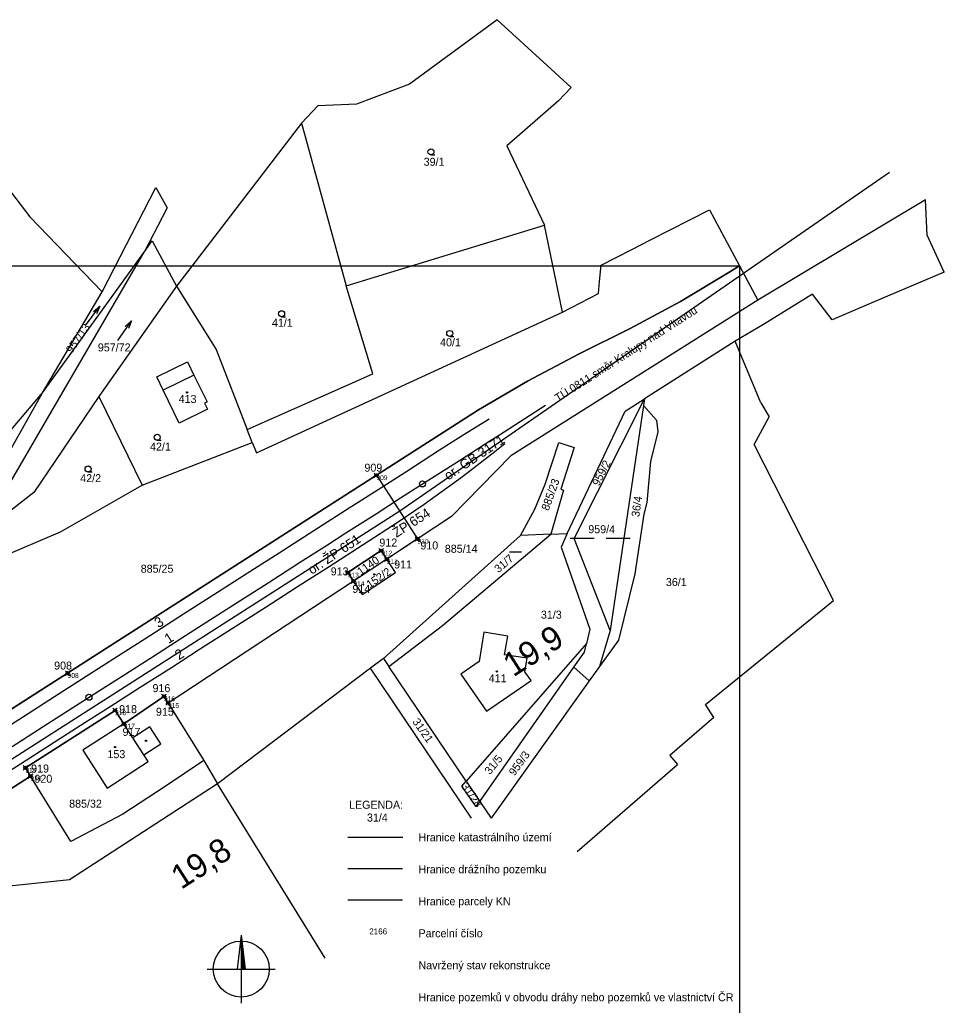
# Model space of a CAD drawing. Extents: x -752184 to -751416, y -1028299 to -1027836.
# Drawn here: x -751646.8 to -751415.5, y -1028082.5 to -1027836.1 of the extents above; entities that cross this region are included whole.
import ezdxf

# ---------------------------------------------------------------- set-up
doc = ezdxf.new("R2010")
doc.units = 0
for name, color, linetype in [('02_Osa_koleje', 7, 'Continuous'), ('03_Staničení', 7, 'Continuous'), ('Legenda', 7, 'Continuous'), ('Legenda 1', 7, 'Continuous'), ('Legenda 2', 7, 'Continuous'), ('Obvod stavby', 7, 'Continuous'), ('Vrstva 4', 7, 'Continuous'), ('Vrstva 53', 7, 'Continuous'), ('Vrstva 55', 7, 'Continuous'), ('Vrstva 56', 7, 'Continuous'), ('Vrstva 57', 7, 'Continuous'), ('Vrstva 58', 7, 'Continuous'), ('Vrstva 59', 7, 'Continuous'), ('Vrstva 60', 7, 'Continuous'), ('Vrstva 63', 7, 'Continuous'), ('VYT-BODY', 7, 'Continuous')]:
    doc.layers.add(name, color=color, linetype=linetype)

msp = doc.modelspace()

# ---------------------------------------------------------------- linework, layer by layer
at = {"layer": '02_Osa_koleje'}
for p, q in [((-751535.5, -1027939.59), (-751529.38, -1027935.82)), ((-751541.77, -1027943.62), (-751535.5, -1027939.59)), ((-751536.85, -1027946.23), (-751529.25, -1027941.37)), ((-751527.97, -1027944.03), (-751525.45, -1027941.98)), ((-751550.25, -1027949.06), (-751541.77, -1027943.62)), ((-751536.02, -1027950.26), (-751527.97, -1027944.03)), ((-751544.45, -1027951.09), (-751536.85, -1027946.23)), ((-751557.18, -1027953.5), (-751550.25, -1027949.06)), ((-751551.57, -1027955.64), (-751544.45, -1027951.09)), ((-751545.62, -1027957.19), (-751536.02, -1027950.26)), ((-751565.35, -1027958.72), (-751557.18, -1027953.5)), ((-751557.44, -1027959.4), (-751551.57, -1027955.64)), ((-751573.24, -1027963.75), (-751565.35, -1027958.72)), ((-751565.26, -1027964.39), (-751557.44, -1027959.4)), ((-751552.14, -1027961.63), (-751545.62, -1027957.19)), ((-751560.92, -1027967.3), (-751552.14, -1027961.63)), ((-751581.95, -1027969.31), (-751573.24, -1027963.75)), ((-751569.81, -1027967.31), (-751565.26, -1027964.39)), ((-751576.84, -1027971.8), (-751569.81, -1027967.31)), ((-751569.42, -1027972.75), (-751560.92, -1027967.3)), ((-751588.99, -1027973.81), (-751581.95, -1027969.31)), ((-751597.35, -1027979.15), (-751588.99, -1027973.81)), ((-751584.69, -1027976.81), (-751576.84, -1027971.8)), ((-751577.55, -1027977.95), (-751569.42, -1027972.75)), ((-751592.46, -1027981.78), (-751584.69, -1027976.81)), ((-751585.46, -1027983), (-751577.55, -1027977.95)), ((-751605.88, -1027984.61), (-751597.35, -1027979.15)), ((-751599.97, -1027986.58), (-751592.46, -1027981.78)), ((-751593.8, -1027988.33), (-751585.46, -1027983)), ((-751614.37, -1027990.06), (-751605.88, -1027984.61)), ((-751606.23, -1027990.59), (-751599.97, -1027986.58)), ((-751601.83, -1027993.46), (-751593.8, -1027988.33)), ((-751622.32, -1027995.15), (-751614.37, -1027990.06)), ((-751613.64, -1027995.33), (-751606.23, -1027990.59)), ((-751608.88, -1027997.98), (-751601.83, -1027993.46)), ((-751630.17, -1028000.17), (-751622.32, -1027995.15)), ((-751621.23, -1028000.17), (-751613.64, -1027995.33)), ((-751616.69, -1028002.97), (-751608.88, -1027997.98)), ((-751636.92, -1028004.49), (-751630.17, -1028000.17)), ((-751626.18, -1028003.34), (-751621.23, -1028000.17)), ((-751633.49, -1028008.01), (-751626.18, -1028003.34)), ((-751624.19, -1028007.75), (-751616.69, -1028002.97)), ((-751645.91, -1028010.23), (-751636.92, -1028004.49)), ((-751640.92, -1028012.76), (-751633.49, -1028008.01)), ((-751630.51, -1028011.79), (-751624.19, -1028007.75)), ((-751653.82, -1028015.29), (-751645.91, -1028010.23)), ((-751648.69, -1028017.73), (-751640.92, -1028012.76)), ((-751638.2, -1028016.71), (-751630.51, -1028011.79)), ((-751646.64, -1028022.11), (-751638.2, -1028016.71)), ((-751655.05, -1028027.47), (-751646.64, -1028022.11))]:
    msp.add_line(p, q, dxfattribs=at)
msp.add_lwpolyline([(-751529.25, -1027941.37), (-751526.83, -1027939.82), (-751515.32, -1027932.45)], dxfattribs=at)
at = {"layer": '03_Staničení'}
for centre in [(-751546.08, -1027952.12), (-751629.49, -1028005.46)]:
    msp.add_circle(centre, 0.75, dxfattribs=at)
at = {"layer": 'Legenda 1'}
for p, q in [((-751591.4, -1028064.89), (-751592.4, -1028073.39)), ((-751591.4, -1028064.89), (-751591.4, -1028081.89)), ((-751591.4, -1028064.89), (-751590.39, -1028073.39)), ((-751591.4, -1028067.02), (-751590.64, -1028073.39)), ((-751591.4, -1028069.14), (-751590.89, -1028073.39)), ((-751591.4, -1028071.27), (-751591.15, -1028073.39)), ((-751599.9, -1028073.39), (-751582.9, -1028073.39)), ((-751591.4, -1028073.39), (-751591.4, -1028073.39))]:
    msp.add_line(p, q, dxfattribs=at)
msp.add_circle((-751591.4, -1028073.39), 7, dxfattribs=at)
at = {"layer": 'Obvod stavby'}
msp.add_lwpolyline([(-751669.8, -1028021.76), (-751634.83, -1027999.42), (-751557.58, -1027949.97), (-751547.3, -1027965.87), (-751554.98, -1027970.94), (-751556.39, -1027968.8), (-751564.74, -1027974.3), (-751563.33, -1027976.45), (-751609.72, -1028006.9), (-751610.74, -1028005.23), (-751620.78, -1028012.09), (-751622.97, -1028008.73), (-751645.38, -1028023.11), (-751644.14, -1028025.2), (-751657.66, -1028033.82)], dxfattribs=at)
at = {"layer": 'Vrstva 4'}
msp.add_lwpolyline([(-751880.79, -1027897.6), (-751466.79, -1027897.6), (-751466.79, -1028188.6), (-751880.79, -1028188.6)], close=True, dxfattribs=at)
at = {"layer": 'Vrstva 53'}
msp.add_line((-751564.73, -1028048.27), (-751551.03, -1028048.27), dxfattribs=at)
for points in [[(-751934.1, -1028186.19), (-751914.9, -1028176.41), (-751903.43, -1028170.23), (-751901.96, -1028169.44), (-751904.77, -1028166.14), (-751893.52, -1028163.47), (-751890.97, -1028163.13), (-751806.75, -1028109.29), (-751808.53, -1028106.05), (-751798.29, -1028099.68), (-751750.57, -1028069.21), (-751709.61, -1028036.63), (-751702.85, -1028029.39), (-751690.7, -1028035.11), (-751634.83, -1027999.42), (-751532.07, -1027933.64), (-751519.82, -1027926.47), (-751506.87, -1027919.58), (-751494.13, -1027913.25), (-751481.54, -1027906.54), (-751469.19, -1027899.14), (-751466.79, -1027897.6)], [(-751462.19, -1027906.18), (-751523.97, -1027945.11), (-751538.82, -1027960.28), (-751554.98, -1027970.94), (-751563.33, -1027976.45), (-751609.72, -1028006.9), (-751600.73, -1028021.25), (-751610.42, -1028027.79), (-751621, -1028034.71), (-751634.07, -1028041.54), (-751644.14, -1028025.2), (-751657.66, -1028033.82)]]:
    msp.add_lwpolyline(points, dxfattribs=at)
at = {"layer": 'Vrstva 55'}
for p, q in [((-751514.9, -1027847.48), (-751527.35, -1027836.07)), ((-751514.9, -1027847.48), (-751508.89, -1027852.99)), ((-751670.74, -1027850.8), (-751644.31, -1027885.35)), ((-751572.26, -1027857.64), (-751576.37, -1027861.95)), ((-751576.37, -1027861.95), (-751607.59, -1027902.71)), ((-751576.37, -1027861.95), (-751565.18, -1027902.61)), ((-751626.22, -1027904.08), (-751612.77, -1027878.04)), ((-751612.77, -1027878.04), (-751609.94, -1027883.14)), ((-751420.23, -1027881.1), (-751462.19, -1027906.18)), ((-751419.83, -1027889.96), (-751420.23, -1027881.1)), ((-751626.22, -1027904.08), (-751644.31, -1027885.35)), ((-751609.94, -1027883.14), (-751615.69, -1027894.18)), ((-751489.04, -1027891.13), (-751474.31, -1027883.58)), ((-751474.31, -1027883.58), (-751466.79, -1027897.6)), ((-751565.18, -1027902.61), (-751515.53, -1027887.47)), ((-751511.01, -1027909.22), (-751515.53, -1027887.47)), ((-751415.54, -1027899.18), (-751419.83, -1027889.96)), ((-751615.69, -1027894.18), (-751613.65, -1027891.36)), ((-751613.65, -1027891.36), (-751607.59, -1027902.71)), ((-751493.66, -1027893.5), (-751489.04, -1027891.13)), ((-751656.71, -1027964.65), (-751615.69, -1027894.18)), ((-751641.14, -1027929.37), (-751615.69, -1027894.18)), ((-751466.79, -1027897.6), (-751469.19, -1027899.14)), ((-751466.79, -1027897.6), (-751462.19, -1027906.18)), ((-751607.59, -1027902.71), (-751626.99, -1027930.26)), ((-751641.14, -1027929.37), (-751626.22, -1027904.08)), ((-751460.76, -1027912.3), (-751467.89, -1027916.43)), ((-751467.89, -1027916.43), (-751490.52, -1027930.81)), ((-751461.44, -1027931.84), (-751467.89, -1027916.43)), ((-751612.52, -1027925.39), (-751604.88, -1027921.62)), ((-751626.99, -1027930.26), (-751616.15, -1027952.42)), ((-751490.52, -1027930.81), (-751490.76, -1027932.54)), ((-751461.44, -1027931.84), (-751459.38, -1027935.34)), ((-751490.76, -1027932.54), (-751499.13, -1027988.78)), ((-751588.69, -1027941.76), (-751589.95, -1027938.49)), ((-751616.15, -1027952.42), (-751588.69, -1027941.76)), ((-751510.79, -1027953.68), (-751513.96, -1027964.72)), ((-751521.54, -1027965.05), (-751517.93, -1027958.42)), ((-751521.54, -1027965.05), (-751555.86, -1027995.74)), ((-751513.96, -1027964.72), (-751521.54, -1027965.05)), ((-751513.96, -1027964.72), (-751509.88, -1027964.53)), ((-751554.98, -1027970.94), (-751563.33, -1027976.45)), ((-751563.33, -1027976.45), (-751609.72, -1028006.9)), ((-751499.13, -1027988.78), (-751501.78, -1027997.8)), ((-751505.06, -1027992), (-751535.11, -1028026.46)), ((-751555.86, -1027995.74), (-751559.11, -1027998.2)), ((-751555.86, -1027995.74), (-751554.45, -1027997.78)), ((-751559.11, -1027998.2), (-751597.31, -1028027.06)), ((-751535.11, -1028026.46), (-751554.45, -1027997.78)), ((-751531.7, -1028031.5), (-751508.24, -1027997.97)), ((-751508.24, -1027997.97), (-751504.35, -1028001.39)), ((-751501.78, -1027997.8), (-751504.35, -1028001.39)), ((-751504.35, -1028001.39), (-751528.9, -1028035.64)), ((-751610.74, -1028005.23), (-751609.72, -1028006.9)), ((-751609.72, -1028006.9), (-751600.73, -1028021.25)), ((-751600.73, -1028021.25), (-751597.31, -1028027.06)), ((-751570.45, -1028070.69), (-751597.31, -1028027.06)), ((-751535.11, -1028026.46), (-751531.7, -1028031.5)), ((-751531.7, -1028031.5), (-751532.76, -1028032.72)), ((-751531.7, -1028031.5), (-751528.9, -1028035.64)), ((-751564.71, -1028040.45), (-751551.01, -1028040.45)), ((-751564.75, -1028056.09), (-751551.05, -1028056.09))]:
    msp.add_line(p, q, dxfattribs=at)
for points in [[(-751527.35, -1027836.07), (-751549.35, -1027852.19), (-751562.57, -1027857.16), (-751572.26, -1027857.64)], [(-751508.89, -1027852.99), (-751512.04, -1027856.33), (-751525.01, -1027867.6), (-751515.53, -1027887.47)], [(-751511.01, -1027909.22), (-751502.05, -1027904.53), (-751501.8, -1027901.52), (-751501.41, -1027897.47), (-751493.66, -1027893.5)], [(-751469.19, -1027899.14), (-751481.54, -1027906.54), (-751494.13, -1027913.25), (-751506.87, -1027919.58), (-751519.82, -1027926.47), (-751532.07, -1027933.64), (-751634.83, -1027999.42), (-751690.7, -1028035.11), (-751702.85, -1028029.39)], [(-751415.54, -1027899.18), (-751429.76, -1027905.22), (-751434.82, -1027907.37), (-751443.56, -1027911.08)], [(-751607.59, -1027902.71), (-751597.69, -1027918.48), (-751589.95, -1027938.49)], [(-751589.95, -1027938.49), (-751558.45, -1027924.61), (-751565.18, -1027902.61)], [(-751443.56, -1027911.08), (-751448.52, -1027904.72), (-751460.76, -1027912.3)], [(-751462.19, -1027906.18), (-751523.97, -1027945.11), (-751538.82, -1027960.28), (-751554.98, -1027970.94)], [(-751588.69, -1027941.76), (-751587.61, -1027944.36), (-751511.01, -1027909.22)], [(-751604.88, -1027921.62), (-751603.25, -1027924.91), (-751599.95, -1027931.6), (-751600.61, -1027931.93), (-751599.87, -1027933.41), (-751606.96, -1027936.93), (-751610.94, -1027928.67), (-751612.52, -1027925.39)], [(-751672, -1027960.17), (-751661.99, -1027953.87), (-751641.14, -1027929.37)], [(-751668.79, -1027968.97), (-751658.03, -1027959.34), (-751641.14, -1027929.37)], [(-751626.99, -1027930.26), (-751643.3, -1027954.3), (-751656.71, -1027964.65)], [(-751509.88, -1027964.53), (-751495.38, -1027933.9), (-751490.52, -1027930.81)], [(-751499.13, -1027988.78), (-751508.14, -1027965.79), (-751490.52, -1027930.81)], [(-751490.76, -1027932.54), (-751487.53, -1027936.17), (-751487.21, -1027939.13), (-751489.07, -1027946.51), (-751489.95, -1027956.74), (-751490.69, -1027959.66), (-751492.95, -1027974.6), (-751497.03, -1027991.17), (-751501.78, -1027997.8)], [(-751473.18, -1028010.52), (-751475.29, -1028007.29), (-751443.25, -1027981.25), (-751463.14, -1027942.28), (-751459.38, -1027935.34)], [(-751517.93, -1027958.42), (-751515.42, -1027952.2), (-751511.94, -1027941.75), (-751508.1, -1027943), (-751511.47, -1027953.46), (-751510.79, -1027953.68)], [(-751651.99, -1027970.58), (-751636.62, -1027964.12), (-751616.15, -1027952.42)], [(-751554.45, -1027997.78), (-751541.05, -1027987.48), (-751513.96, -1027964.72)], [(-751509.88, -1027964.53), (-751511.41, -1027967.96), (-751504.21, -1027988.42), (-751505.06, -1027992)], [(-751563.33, -1027976.45), (-751564.74, -1027974.3), (-751556.39, -1027968.8), (-751554.98, -1027970.94)], [(-751563.33, -1027976.45), (-751561.13, -1027979.79), (-751552.78, -1027974.28), (-751554.98, -1027970.94)], [(-751530.72, -1027989.19), (-751531.91, -1027996.52), (-751536.51, -1027999.67), (-751530.08, -1028008.97), (-751518.89, -1028001.3), (-751520.44, -1027999.07), (-751519.9, -1027995.71), (-751525.59, -1027994.81), (-751524.75, -1027990.16), (-751530.72, -1027989.19)], [(-751508.24, -1027997.97), (-751505.57, -1027994.16), (-751505.06, -1027992)], [(-751533.79, -1028035.7), (-751559.11, -1027998.2)], [(-751622.97, -1028008.73), (-751620.78, -1028012.09), (-751610.74, -1028005.23)], [(-751644.14, -1028025.2), (-751645.38, -1028023.11), (-751622.97, -1028008.73)], [(-751473.18, -1028010.52), (-751484.17, -1028020.02), (-751482.24, -1028022.26)], [(-751611.54, -1028017.13), (-751614.28, -1028012.89), (-751618.5, -1028015.62), (-751620.78, -1028012.09), (-751631.03, -1028018.71), (-751624.93, -1028028.16), (-751614.68, -1028021.54), (-751615.76, -1028019.86), (-751611.54, -1028017.13)], [(-751600.73, -1028021.25), (-751610.42, -1028027.79), (-751621, -1028034.71), (-751634.07, -1028041.54), (-751644.14, -1028025.2)], [(-751507.37, -1028043.99), (-751482.24, -1028022.26)], [(-751811.98, -1028131.93), (-751700.39, -1028060.59), (-751700.15, -1028061), (-751685.1, -1028051.35), (-751685.36, -1028050.92), (-751657.93, -1028033.4), (-751657.66, -1028033.82), (-751644.14, -1028025.2)], [(-751597.31, -1028027.06), (-751634.36, -1028051.12), (-751685.04, -1028056.42), (-751698.4, -1028064.61)], [(-751532.76, -1028032.72), (-751536.2, -1028027.71), (-751535.11, -1028026.46)]]:
    msp.add_lwpolyline(points, dxfattribs=at)
at = {"layer": 'Vrstva 56'}
for p, q in [((-751603.25, -1027924.91), (-751610.94, -1027928.67)), ((-751615.76, -1028019.86), (-751618.5, -1028015.62))]:
    msp.add_line(p, q, dxfattribs=at)
at = {"layer": 'Vrstva 58'}
for p, q in [((-751543.94, -1027869.85), (-751542.94, -1027869.85)), ((-751630.38, -1027912.48), (-751626.78, -1027907.68)), ((-751622.31, -1027916.3), (-751618.89, -1027911.37)), ((-751581.3, -1027910.33), (-751580.3, -1027910.33)), ((-751539.26, -1027915.25), (-751538.26, -1027915.25)), ((-751612.42, -1027941.21), (-751611.42, -1027941.21)), ((-751629.72, -1027949.14), (-751628.72, -1027949.14)), ((-751509.14, -1027965.72), (-751503.14, -1027965.72)), ((-751500.14, -1027965.72), (-751494.14, -1027965.72)), ((-751524.26, -1027969.13), (-751521.26, -1027969.13))]:
    msp.add_line(p, q, dxfattribs=at)
for points in [[(-751628.38, -1027908.98), (-751626.78, -1027907.68), (-751627.58, -1027909.58)], [(-751620.44, -1027912.73), (-751618.89, -1027911.37), (-751619.62, -1027913.3)]]:
    msp.add_lwpolyline(points, dxfattribs=at)
for centre in [(-751543.94, -1027869.1), (-751581.3, -1027909.58), (-751539.26, -1027914.5), (-751612.42, -1027940.46), (-751629.72, -1027948.39)]:
    msp.add_circle(centre, 0.75, dxfattribs=at)
at = {"layer": 'Vrstva 59'}
for centre in [(-751604.94, -1027929.24), (-751558.09, -1027974.76), (-751527.47, -1027999), (-751622.96, -1028017.93), (-751615.24, -1028016.34)]:
    msp.add_circle(centre, 0.175, dxfattribs=at)
at = {"layer": 'Vrstva 60'}
for p, q in [((-751557.58, -1027949.97), (-751557.58, -1027949.97)), ((-751547.3, -1027965.87), (-751547.3, -1027965.87)), ((-751556.39, -1027968.8), (-751556.39, -1027968.8)), ((-751554.98, -1027970.94), (-751554.98, -1027970.94)), ((-751564.74, -1027974.3), (-751564.74, -1027974.3)), ((-751563.33, -1027976.45), (-751563.33, -1027976.45)), ((-751634.83, -1027999.42), (-751634.83, -1027999.42)), ((-751610.74, -1028005.23), (-751610.74, -1028005.23)), ((-751609.72, -1028006.9), (-751609.72, -1028006.9)), ((-751622.97, -1028008.73), (-751622.97, -1028008.73)), ((-751620.78, -1028012.09), (-751620.78, -1028012.09)), ((-751645.38, -1028023.11), (-751645.38, -1028023.11)), ((-751644.14, -1028025.2), (-751644.14, -1028025.2))]:
    msp.add_line(p, q, dxfattribs=at)
at = {"layer": 'Vrstva 63'}
for p, q in [((-751429.27, -1027874.23), (-751551.77, -1027958.95)), ((-751551.77, -1027958.95), (-751975.84, -1028230))]:
    msp.add_line(p, q, dxfattribs=at)
at = {"layer": 'VYT-BODY'}
for p, q in [((-751557.01, -1027949.4), (-751558.15, -1027950.53)), ((-751557.01, -1027950.54), (-751558.15, -1027949.4)), ((-751546.73, -1027965.31), (-751547.87, -1027966.44)), ((-751546.73, -1027966.44), (-751547.86, -1027965.31)), ((-751555.82, -1027968.23), (-751556.96, -1027969.37)), ((-751555.82, -1027969.37), (-751556.96, -1027968.23)), ((-751554.41, -1027970.37), (-751555.55, -1027971.51)), ((-751554.41, -1027971.51), (-751555.55, -1027970.37)), ((-751564.17, -1027973.73), (-751565.31, -1027974.87)), ((-751564.17, -1027974.87), (-751565.31, -1027973.73)), ((-751562.76, -1027975.88), (-751563.9, -1027977.02)), ((-751562.76, -1027977.02), (-751563.9, -1027975.88)), ((-751634.26, -1027998.85), (-751635.4, -1027999.99)), ((-751634.26, -1027999.99), (-751635.4, -1027998.85)), ((-751610.17, -1028004.66), (-751611.31, -1028005.8)), ((-751610.17, -1028005.8), (-751611.31, -1028004.66)), ((-751622.4, -1028008.16), (-751623.54, -1028009.3)), ((-751622.4, -1028009.3), (-751623.54, -1028008.16)), ((-751609.15, -1028006.33), (-751610.29, -1028007.47)), ((-751609.15, -1028007.47), (-751610.29, -1028006.33)), ((-751620.21, -1028011.52), (-751621.35, -1028012.66)), ((-751620.21, -1028012.66), (-751621.35, -1028011.52)), ((-751644.81, -1028022.54), (-751645.95, -1028023.68)), ((-751644.81, -1028023.68), (-751645.95, -1028022.54)), ((-751643.57, -1028024.63), (-751644.71, -1028025.77)), ((-751643.57, -1028025.77), (-751644.71, -1028024.63))]:
    msp.add_line(p, q, dxfattribs=at)
for centre in [(-751557.58, -1027949.97), (-751547.3, -1027965.87), (-751556.39, -1027968.8), (-751554.98, -1027970.94), (-751564.74, -1027974.3), (-751563.33, -1027976.45), (-751634.83, -1027999.42), (-751610.74, -1028005.23), (-751622.97, -1028008.73), (-751609.72, -1028006.9), (-751620.78, -1028012.09), (-751645.38, -1028023.11), (-751644.14, -1028025.2)]:
    msp.add_circle(centre, 0.4, dxfattribs=at)

# ---------------------------------------------------------------- texts
at = {"layer": '02_Osa_koleje'}
for s, height, rotation, p in [('TÚ 0811 směr Kralupy nad Vltavou', 2, 32.6028, (-751512.17, -1027931.68)), ('3', 2.5, 32.6084, (-751612.12, -1027988.22)), ('1', 2.5, 32.6084, (-751609.6, -1027992.17)), ('2', 2.5, 32.6084, (-751607, -1027996.23))]:
    msp.add_text(s, height=height, rotation=rotation, dxfattribs=at).set_placement(p)
at = {"layer": '03_Staničení'}
for s, rotation, p in [('19,9', 32.5948, (-751523.37, -1028000.52)), ('19,8', 32.5903, (-751606.44, -1028053.63))]:
    msp.add_text(s, height=6, rotation=rotation, dxfattribs=at).set_placement(p)
at = {"layer": 'Legenda'}
for s, p in [('Hranice katastrálního území', (-751547.06, -1028041.45)), ('Hranice drážního pozemku', (-751547.06, -1028049.45)), ('Hranice parcely KN', (-751547.06, -1028057.45)), ('Parcelní číslo', (-751547.06, -1028065.45)), ('Navržený stav rekonstrukce', (-751547.06, -1028073.45)), ('Hranice pozemků v obvodu dráhy nebo pozemků ve vlastnictví ČR', (-751547.06, -1028081.45))]:
    msp.add_text(s, height=2, rotation=360, dxfattribs=at).set_placement(p)
at = {"layer": 'Legenda 2'}
msp.add_text('LEGENDA:', height=2, rotation=360, dxfattribs=at).set_placement((-751564.44, -1028033.33))
at = {"layer": 'Obvod stavby'}
for s, p in [('909', (-751560.59, -1027949.06)), ('912', (-751556.86, -1027967.78)), ('910', (-751546.6, -1027968.5)), ('911', (-751553.16, -1027973.26)), ('913', (-751569.03, -1027974.99)), ('914', (-751563.6, -1027979.35)), ('908', (-751638.21, -1027998.53)), ('916', (-751613.6, -1028004.17)), ('918', (-751621.95, -1028009.43)), ('915', (-751612.74, -1028010.07)), ('917', (-751621.09, -1028015.12)), ('919', (-751643.96, -1028024.27)), ('920', (-751643.13, -1028026.83))]:
    msp.add_text(s, height=2, dxfattribs=at).set_placement(p)
at = {"layer": 'Vrstva 57'}
for s, p in [('39/1', (-751545.77, -1027872.58)), ('41/1', (-751583.73, -1027912.82)), ('957/72', (-751627.27, -1027918.99)), ('40/1', (-751541.66, -1027917.71)), ('413', (-751607.06, -1027931.88)), ('42/1', (-751614.22, -1027943.8)), ('42/2', (-751631.68, -1027951.68)), ('959/4', (-751504.59, -1027964.44)), ('885/14', (-751540.48, -1027969.33)), ('885/25', (-751616.55, -1027974.32)), ('36/1', (-751485.18, -1027977.65)), ('31/3', (-751516.45, -1027985.8)), ('411', (-751529.5, -1028001.7)), ('153', (-751624.87, -1028020.68)), ('885/32', (-751634.45, -1028033.06)), ('31/4', (-751559.96, -1028036.52))]:
    msp.add_text(s, height=2, dxfattribs=at).set_placement(p)
for s, height, rotation, p in [('957/13', 2, 55, (-751633.78, -1027919.63)), ('959/2', 2, 63, (-751501.94, -1027952.82)), ('885/23', 2, 70, (-751514.54, -1027958.96)), ('36/4', 2, 82, (-751491.85, -1027960.48)), ('1140', 2, 35, (-751561.53, -1027975.07)), ('31/7', 2, 40, (-751527.07, -1027974.47)), ('152/2', 2, 34, (-751559.27, -1027978.29)), ('31/21', 2, 305, (-751548.68, -1028011.57)), ('31/5', 2, 51, (-751529.18, -1028024.94)), ('959/3', 2, 54, (-751523.04, -1028025.25)), ('31/28', 2, 305, (-751536.47, -1028027.74)), ('2166', 1.5, 360, (-751559.38, -1028064.74))]:
    msp.add_text(s, height=height, rotation=rotation, dxfattribs=at).set_placement(p)
at = {"layer": 'Vrstva 60'}
for s, p in [('909', (-751557.58, -1027951.17)), ('910', (-751547.3, -1027967.07)), ('912', (-751556.39, -1027970)), ('911', (-751554.98, -1027972.14)), ('913', (-751564.74, -1027975.5)), ('914', (-751563.33, -1027977.65)), ('908', (-751634.83, -1028000.62)), ('916', (-751610.74, -1028006.43)), ('915', (-751609.72, -1028008.1)), ('918', (-751622.97, -1028009.93)), ('917', (-751620.78, -1028013.29)), ('919', (-751645.38, -1028024.31)), ('920', (-751644.14, -1028026.4))]:
    msp.add_text(s, height=1.2, dxfattribs=at).set_placement(p)
at = {"layer": 'Vrstva 63'}
for s, rotation, p in [('or. GB 3171', 33.8047, (-751539.62, -1027951.3)), ('ŽP 654', 32.593, (-751552.57, -1027965.62)), ('or. ŽP 651', 33.8047, (-751573.73, -1027974.87))]:
    msp.add_text(s, height=2.4, rotation=rotation, dxfattribs=at).set_placement(p)

doc.saveas('drawing.dxf')
